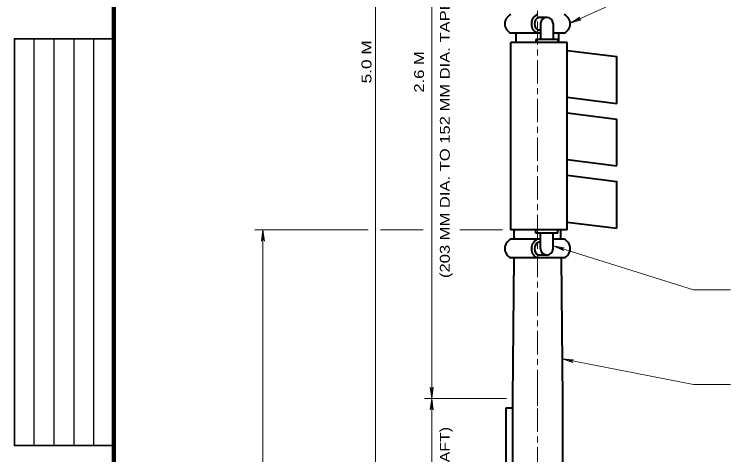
# Model space of a CAD drawing. Extents: x 312583 to 312853, y 144419 to 144586.
# Drawn here: x 312608.9 to 312664.4, y 144490 to 144523.7 of the extents above; entities that cross this region are included whole.
import ezdxf

# ---------------------------------------------------------------- set-up
doc = ezdxf.new("R2010")
doc.units = 0
doc.header["$LTSCALE"] = 0.3
doc.linetypes.add('LONG_DASH_SHORT_DASH', pattern=[9.9, 6, -1.2, 1.5, -1.2])
doc.layers.add('1', color=7, linetype='Continuous', lineweight=40)
doc.layers.add('2', color=7, linetype='Continuous', lineweight=13)

msp = doc.modelspace()

# ---------------------------------------------------------------- linework, layer by layer
at = {"layer": '1'}
for p, q in [((312649.7234, 144523.5243), (312649.1024, 144523.5243)), ((312649.2481, 144523.0489), (312649.2481, 144521.8299)), ((312650.2064, 144523.0413), (312650.2064, 144521.8299)), ((312649.2481, 144522.5276), (312649.1024, 144522.5276)), ((312649.2481, 144522.3053), (312646.9711, 144522.3053)), ((312647.3621, 144521.5846), (312647.3698, 144522.3053)), ((312650.5668, 144521.8299), (312648.8878, 144521.8299)), ((312648.8878, 144521.8299), (312648.8878, 144521.5846)), ((312651.0421, 144522.3053), (312650.2064, 144522.3053)), ((312650.5668, 144521.8299), (312650.5668, 144521.5846)), ((312650.6511, 144521.5846), (312650.6434, 144522.3129)), ((312651.2721, 144521.5846), (312646.9634, 144521.5846)), ((312646.9634, 144507.2096), (312646.9634, 144521.5846)), ((312651.2721, 144521.5846), (312646.9634, 144521.5846)), ((312651.2721, 144507.2096), (312651.2721, 144521.5846)), ((312651.2721, 144520.9866), (312655.1054, 144520.5113)), ((312655.1054, 144516.9156), (312655.1054, 144520.5113)), ((312651.2721, 144517.3986), (312655.1054, 144516.9156)), ((312651.2721, 144516.1949), (312655.1054, 144515.7196)), ((312655.1054, 144512.1546), (312655.1054, 144515.7196)), ((312651.2721, 144512.6069), (312655.1054, 144512.1239)), ((312651.2721, 144511.4033), (312655.1054, 144510.9279)), ((312655.1054, 144507.3323), (312655.1054, 144510.9586)), ((312651.2721, 144507.8153), (312655.1054, 144507.3323)), ((312651.2721, 144507.2096), (312646.9634, 144507.2096)), ((312647.2164, 144506.4966), (312647.2164, 144507.2096)), ((312648.8878, 144506.9719), (312648.8878, 144507.2096)), ((312650.5668, 144506.9719), (312648.8878, 144506.9719)), ((312649.2481, 144505.7529), (312649.2481, 144506.9719)), ((312650.2064, 144505.7529), (312650.2064, 144506.9719)), ((312650.5668, 144506.9719), (312650.5668, 144507.2096)), ((312650.8044, 144506.4966), (312650.7968, 144507.2096)), ((312649.2481, 144506.4966), (312646.9711, 144506.4966)), ((312649.2481, 144506.2743), (312649.1024, 144506.2743)), ((312651.0421, 144506.4966), (312650.2064, 144506.4966)), ((312649.7234, 144505.2776), (312649.1024, 144505.2776)), ((312651.0421, 144505.0553), (312646.9711, 144505.0553)), ((312647.2011, 144505.0553), (312647.0938, 144494.2759)), ((312650.8198, 144505.0553), (312650.9271, 144494.2759)), ((312647.0938, 144494.2759), (312647.0938, 144473.6679)), ((312650.9271, 144494.2759), (312650.9271, 144473.6679)), ((312646.6108, 144493.5553), (312647.0938, 144493.5553)), ((312646.6108, 144487.8053), (312646.6108, 144493.5553))]:
    msp.add_line(p, q, dxfattribs=at)
at = {"layer": '1', "lineweight": 25}
for p, q in [((312610.4087, 144490.6573), (312610.4087, 144521.8756)), ((312611.9315, 144490.6573), (312611.9315, 144521.8756)), ((312613.4543, 144490.6573), (312613.4543, 144521.8756)), ((312614.9772, 144490.6573), (312614.9772, 144521.8756))]:
    msp.add_line(p, q, dxfattribs=at)
at = {"layer": '1', "lineweight": 158}
msp.add_lwpolyline([(312616.5, 144423.1446), (312616.5, 144585.0846), (312849, 144585.0846)], dxfattribs=at)
at = {"layer": '1', "lineweight": 35}
msp.add_lwpolyline([(312616.5, 144490.6573), (312608.8858, 144490.6573), (312608.8858, 144521.8756), (312616.5, 144521.8756)], dxfattribs=at)
at = {"layer": '1'}
for centre, radius, start, end in [((312647.2851, 144523.025), 0.7836, 113.47025, 246.52975), ((312649.3192, 144523.025), 0.7836, 113.47025, 246.52975), ((312649.3192, 144523.025), 0.544, 113.47025, 246.52975), ((312649.7261, 144523.0444), 0.4792, 0.02865, 179.22617), ((312650.7291, 144523.025), 0.7836, 293.47025, 66.52975), ((312647.2851, 144505.775), 0.7836, 113.47025, 246.52975), ((312649.3192, 144505.775), 0.7836, 113.47025, 246.52975), ((312649.3192, 144505.775), 0.544, 113.47025, 246.52975), ((312650.7291, 144505.775), 0.7836, 293.47025, 66.52975), ((312649.7261, 144505.7556), 0.4792, 180.77383, 359.97135)]:
    msp.add_arc(centre, radius, start, end, dxfattribs=at)
at = {"layer": '2', "linetype": 'LONG_DASH_SHORT_DASH'}
msp.add_line((312649.0104, 144438.2556), (312649.0104, 144579.5523), dxfattribs=at)
at = {"layer": '2'}
for p, q in [((312636.5751, 144471.2759), (312636.5751, 144564.8323)), ((312640.8914, 144494.2759), (312640.8914, 144542.1926)), ((312660.9781, 144527.3883), (312651.5098, 144523.0796)), ((312651.5098, 144523.0796), (312652.2534, 144523.5396)), ((312652.2534, 144523.5396), (312652.0464, 144523.3249)), ((312651.5098, 144523.0796), (312652.3454, 144523.3403)), ((312652.3454, 144523.3403), (312652.0464, 144523.3249)), ((312636.0078, 144507.2096), (312627.3291, 144507.2096)), ((312627.9501, 144507.2096), (312627.8428, 144506.3433)), ((312627.9501, 144461.2096), (312627.9501, 144507.2096)), ((312627.9501, 144507.2096), (312628.0574, 144506.3433)), ((312640.2321, 144507.2096), (312636.9738, 144507.2096)), ((312646.3118, 144507.2096), (312643.0475, 144507.2096)), ((312627.8428, 144506.3433), (312627.9501, 144506.6193)), ((312628.0574, 144506.3433), (312627.9501, 144506.6193)), ((312650.2064, 144505.9983), (312650.9961, 144505.6379)), ((312650.2064, 144505.9983), (312651.0651, 144505.8449)), ((312651.0651, 144505.8449), (312650.7661, 144505.8219)), ((312650.9961, 144505.6379), (312650.7661, 144505.8219)), ((312660.9781, 144495.3493), (312650.8964, 144497.3119)), ((312650.8964, 144497.3119), (312651.7244, 144497.0436)), ((312650.8964, 144497.3119), (312651.7628, 144497.2506)), ((312651.7628, 144497.2506), (312651.4714, 144497.1969)), ((312651.7244, 144497.0436), (312651.4714, 144497.1969)), ((312640.7841, 144495.1423), (312640.8914, 144494.8663)), ((312640.8914, 144494.2759), (312640.7841, 144495.1423)), ((312640.9988, 144495.1423), (312640.8914, 144494.8663)), ((312640.8914, 144494.2759), (312640.9988, 144495.1423)), ((312663.8071, 144495.3493), (312660.9781, 144495.3493)), ((312649.0104, 144494.2759), (312649.0104, 144494.8509)), ((312646.6414, 144494.2759), (312640.3471, 144494.2759)), ((312640.8914, 144494.2759), (312640.7841, 144493.4096)), ((312640.8914, 144471.2759), (312640.8914, 144494.2759)), ((312640.8914, 144494.2759), (312640.9988, 144493.4096)), ((312649.0104, 144494.2759), (312649.0104, 144493.7009)), ((312640.7841, 144493.4096), (312640.8914, 144493.6856)), ((312640.9988, 144493.4096), (312640.8914, 144493.6856))]:
    msp.add_line(p, q, dxfattribs=at)
msp.add_lwpolyline([(312663.8071, 144502.6249), (312660.9781, 144502.6249), (312650.2064, 144505.9983)], dxfattribs=at)

# ---------------------------------------------------------------- texts
for s, width, p in [('(203 MM DIA. TO 152 MM DIA. TAPERED SHAFT)', 1.25, (312642.2801, 144503.5195)), ('5.0 M', 1.3, (312636.268, 144518.4561)), ('2.6 M', 1.25, (312640.3046, 144517.7465)), ('(203 MM DIA. STRAIGHT SHAFT)', 1.2, (312642.2801, 144473.3174))]:
    msp.add_text(s, height=0.76, rotation=90, dxfattribs=dict(at, width=width)).set_placement(p)

doc.saveas('drawing.dxf')
